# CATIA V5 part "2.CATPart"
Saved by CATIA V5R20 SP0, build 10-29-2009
Part number: 2
Material "Mirror": density 2190 kg/m3, Young's modulus 6.5e+10 Pa, Poisson ratio 0.161, thermal expansion 8e-05 1/K
Bounding box of the stored display mesh (mm): x -63.753 to 47.232, y -14.262 to 14.262, z 0 to 148
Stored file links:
  E:\Ehsan\Amoozesh\CATIA\CATIA Course\Advanced\Videos\Session-21\2.CATPart
  D:\CATIA V5R20\B20\intel_a\startup\materials\Catalog.CATMaterial
  D:\CATIA V5R20\B20\intel_a\resources\graphic\figures\CATIA_EnvironmentMap_Satin_512x512.jpg
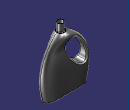
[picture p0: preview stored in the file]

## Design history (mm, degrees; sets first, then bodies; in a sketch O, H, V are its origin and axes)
Set1
  Plane1: type Offset, RefPlane xy-plane, Offset 90
  Plane2: type Offset, RefPlane Plane1, Offset 40
  Sketch1 on xy-plane, origin (0, 0, 0), H (1, 0, 0), V (0, 1, 0)
    spline S1 through (-55, 0) (-54.9948, 0.3662) (-18.438, 12) (15.8383, 12) (39.9937, 0.3676) (40, 0)
    construction line L1 (40, 0) -> (40, 44.099)
    point P1 (40, 0)
    construction line L2 (-55, 0) -> (-55, 44.099)
    point P3 (-55, 0)
    point P5 (-55, 0)
    point P6 (40, 0)
    point P7 (15.8383, 12)
    point P8 (-18.438, 12)
    distance V L2 = 55
    distance V P1 = 40
    distance P7 H = 12
    distance P8 H = 12
    coincidence: P5 H, P6 H, P6 P1, P5 P3
    vertical: L1 V, L2 V
    tangency: S1 L1, S1 L2
  Sketch2 on Plane1, origin (0, 0, 90), H (1, 0, 0), V (0, 1, 0)
    offset curve E1 from Sketch1.S1
  Sketch3 on Plane2, origin (0, 0, 130), H (1, 0, 0), V (0, 1, 0)
    arc A1 centre (0, 0) radius 9 from (9, 0) to (-9, 0) ccw
    construction line L1 (-22.074, 0) -> (22.0228, 0)
    point P1 (-22.074, 0)
    point P3 (-9, 0)
    point P4 (9, 0)
    radius A1 = 9
    coincidence: P1 H, L1 P3, L1 P4
    horizontal: L1 H
  Curve1: Elements Body1
  Curve2: Elements Body1
  Loft1: Sections (Sketch3; Sketch2; Sketch1), Guides (Curve1; Curve2)
  Line1: type PtPt, FirstPoint Sketch1.P5, SecondPoint Sketch1.P6
  Fill1: Boundary (Sketch1; Line1)
  MultiSel1
  Join1: Elements (Loft1; Fill1; {symmetry Reference zx-plane, ToTransfor Loft1}; {symmetry Reference zx-plane, ToTransfor Fill1})
  Sketch4 on Plane2, origin (0, 0, 130), H (1, 0, 0), V (0, 1, 0)
    circle A1 centre (0, 0) radius 7
    reference projected arc E1 centre (0, 0) radius 9 from (-9, 0) to (9, 0) ccw from edge of MultiSel1
    radius A1 = 7
    concentricity: A1 E1
  Extrude1: Lim1 18, Lim2 0, Element1 Sketch4
  Fill2: Boundary (edge of Loft1; edge of MultiSel1)
  Trim1: Trimmed (Fill2; Extrude1)
  Join2: Elements (Join1; Trim1)
  Fillet1: radius 1, on edge [face of Loft1 | face of Fill2]; face of Fill2
  Sketch5 on zx-plane, origin (0, 0, 0), H (-1, 0, 0), V (0, 0, 1)
    ellipse A1 centre (28.3988, 80.6558) semi-axes 37, 17 rotation 304.105
    "Radius" A1 = 37
    "Radius" A1 = 17
  Extrude2: Lim1 18, Lim2 18, Element1 Sketch5
  Trim2: Trimmed (Fillet1; Extrude2)
  Fillet2: radius 3, on face of Extrude2 from Sketch5.A1
  Fillet3: radius 4, on edge [face of Fill1 | face of Loft1]
Body1 (main body), material "Mirror"
  ThickSurface1: Surface Fillet3, TopOffset 1, BotOffset 0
